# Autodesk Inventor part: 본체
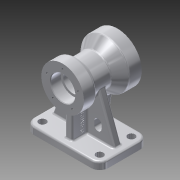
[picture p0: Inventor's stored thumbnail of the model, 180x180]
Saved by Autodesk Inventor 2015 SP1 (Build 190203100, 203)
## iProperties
Created: 2015-08
Part Number: 본체
Material: 알루미늄 6061
Document SubType Name: Modeling
Designer: jun
Density: 2.7 g/cm^3
Appearance: 알루미늄 - 평지
Mass: 1061.97 g
Surface Area: 750.353 cm^2
Volume: 393.324 cm^3
Author: jun
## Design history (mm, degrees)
sketch "스케치1"
  geometry: L1 (-61, 40)-(61, 40); L2 (61, 40)-(61, -40); L3 (61, -40)-(-61, -40); L4 (-61, -40)-(-61, 40); L5 (-61, 40)-(61, -40); 2 further points
  constraints: 10 end point, 2 parallel, 1 coincident, 1 horizontal, 1 midpoint, 1 perpendicular
  dimensions: "d0" = 122 distance of L1.start L1.end; "d1" = 80 distance of L1.end L2.end
extrude "돌출1" new body sketch "스케치1" distance "d2" = 12; taper "d3" = 0 deg
sketch "스케치2"
  geometry: L1 (40, 12)-(40, 0) reference; L2 (40, 0)-(-40, 0) reference; L3 (-40, 0)-(-40, 12) reference; L4 (-40, 12)-(40, 12) reference; L5 (50, 90)-(-40, 90); L6 (50, 90)-(50, 50); L7 (50, 50)-(30, 50); L8 (-40, 90)-(-40, 55); L9 (-40, 55)-(-20, 55); L10 (30, 50)-(13.315, 64); L11 (13.315, 64)-(-14.804, 64); L12 (-14.804, 64)-(-20, 55); L13 (-40, 0)-(-40, 12) reference; 2 further points
  constraints: 16 end point, 2 horizontal, 2 perpendicular, 2 vertical, 1 midpoint, 1 vertical alignment
  dimensions: "d8" = 35 distance of L5.end L8.end; "d9" = 20 distance of L8.end L9.end; "d16" = 60 deg angle of L12 L11; "d103" = 90 distance of L5.start L5.end; "d106" = 90 distance between parallel lines of L2 L5; "d107" = 20 distance of L6.end L7.end; "d108" = 40 deg angle of L10 L11; "d109" = 26 distance between parallel lines of L5 L11; "d110" = 40 distance of L5.start L6.end
revolve "회전1" sketch "스케치2" stored, may be unused: angle "d17" = 90 deg
sketch "스케치3"
  geometry: L1 (61, 12)-(61, 0) reference; L2 (61, 0)-(-61, 0) reference; L3 (-61, 0)-(-61, 12) reference; L4 (-61, 12)-(61, 12) reference; L5 (-25.091, 83.185)-(-51, 12); L6 (-51, 12)-(51, 12); L7 (61, 12)-(-61, 12) reference; L8 (51, 12)-(25.091, 83.185); A1 r 26 centre (0, 90) between (-25.091, 83.185) and (25.091, 83.185) reference; A2 r 26 centre (0, 90) between (-25.091, 83.185) and (25.091, 83.185) reference; 1 further point
  constraints: 6 end point, 4 point on circle, 2 point on line
  dimensions: "d18" = 70 deg angle of L4 L8; "d19" = 70 deg angle of L4 L5; "d20" = 10 distance from line of L3 L5.end; "d21" = 10 distance from line of L1 L6.end
extrude "돌출2" join sketch "스케치3" stored distance "d22" = 12; taper "d23" = 0 deg
sketch "스케치4"
  geometry: L1 (40, 12)-(40, 0) reference; L2 (40, 0)-(-40, 0) reference; L3 (-40, 0)-(-40, 12) reference; L4 (-40, 12)-(-6, 12) reference; L5 (-6, 12)-(-6, 64) reference; L6 (-6, 64)-(-14.804, 64) reference; L7 (-14.804, 64)-(-20, 55) reference; L8 (-20, 55)-(-40, 55) reference; L9 (-40, 55)-(-40, 125) reference; L10 (-40, 125)-(-20, 125) reference; L11 (-20, 125)-(-14.804, 116) reference; L12 (-14.804, 116)-(13.315, 116) reference; L13 (13.315, 116)-(30, 130) reference; L14 (30, 130)-(50, 130) reference; L15 (50, 130)-(50, 50) reference; L16 (50, 50)-(30, 50) reference; L17 (30, 50)-(13.315, 64) reference; L18 (13.315, 64)-(6, 64) reference; L19 (6, 64)-(6, 12) reference; L20 (6, 12)-(40, 12) reference; L21 (-30, 55)-(-30, 12); L22 (36.7, 50)-(30, 12); L23 (40, 12)-(-40, 12) reference; 1 further point
  constraints: 4 end point, 3 point on line, 1 midpoint, 1 perpendicular
  dimensions: "d24" = 80 deg angle of L23 L22; "d25" = 10 distance from line of L22.end L1; "d26" = 10 distance between parallel lines of L3 L21
  node "절단 모서리 투영3"
feature "리브1" dims "d27" = 1, "d28" = 12, "d29" = 0, "d30" = 0, "d31" = 1, "d32" = 1
feature "리브2" dims "d33" = 1, "d34" = 12, "d35" = 0, "d36" = 0, "d37" = 1, "d38" = 1
sketch "스케치5"
  geometry: C1 r 40 at (0, 0) reference; C2 r 26 at (0, 0); 1 further point
  constraints: 1 centre point, 1 coincident
  dimensions: "d39" = 52 diameter of C2
extrude "돌출3" cut sketch "스케치5" distance "d40" = 20; taper "d41" = 0 deg
sketch "스케치6"
  geometry: L1 (-6, 39.547)-(-6, 78) reference; L2 (-6, 78)-(-61, 78) reference; L3 (-61, 78)-(-61, 90) reference; L4 (-61, 90)-(61, 90) reference; L5 (61, 90)-(61, 78) reference; L6 (61, 78)-(6, 78) reference; L7 (6, 78)-(6, 39.547) reference; L8 (6, 78)-(-6, 78) reference; C1 r 26 at (0, 0) reference; C2 r 19 at (0, 0); A1 r 40 centre (0, 0) between (-6, 39.547) and (6, 39.547) reference; 1 further point
  constraints: 1 centre point, 1 coincident
  dimensions: "d42" = 38 diameter of C2
extrude "돌출4" cut sketch "스케치6" distance "d43" = 3; taper "d44" = 0 deg
sketch "스케치7"
  geometry: L1 (-6, 78)-(-61, 78) reference; L2 (-61, 78)-(-61, 90) reference; L3 (-61, 90)-(61, 90) reference; L4 (61, 90)-(61, 78) reference; L5 (61, 78)-(6, 78) reference; L6 (6, 78)-(6, 36.999) reference; L7 (-6, 36.999)-(-6, 78) reference; C1 r 19 at (0, 0) reference; C2 r 16 at (0, 0); A1 r 37.483 centre (0, 0) between (-6, 36.999) and (6, 36.999) reference; 1 further point
  constraints: 1 centre point, 1 coincident
  dimensions: "d45" = 32 diameter of C2
extrude "돌출5" cut sketch "스케치7" stored distance "d46" = 3; taper "d47" = 0 deg
sketch "스케치8"
  geometry: L1 (-61, -78)-(61, -78) reference; L2 (61, -78)-(61, -90) reference; L3 (61, -90)-(-61, -90) reference; L4 (-61, -90)-(-61, -78) reference; C1 r 16 at (0, 0) reference; C2 r 35 at (0, 0) reference; C3 r 20 at (0, 0); 1 further point
  constraints: 1 centre point, 1 coincident
  dimensions: "d48" = 40 diameter of C3
extrude "돌출6" cut sketch "스케치8" distance "d49" = 17; taper "d50" = 0 deg
sketch "스케치9"
  geometry: C1 r 26 at (0, 0) reference; C2 r 40 at (0, 0) reference; 2 further points
  constraints: 1 vertical alignment
  dimensions: "d51" = 33 distance of C1.centre point (0, -33)
hole "구멍1" sketch "스케치9" at (0, -33) diameter "d52" = 3.242; stored, may be unused: countersink angle "d56" = 90 deg, drill point angle "d58" = 118 deg; dims "d53" = 10, "d54" = 4, "d55" = 2, "d57" = 13
sketch "스케치10"
  geometry: L1 (-61, -78)-(61, -78) reference; L2 (61, -78)-(61, -90) reference; L3 (61, -90)-(-61, -90) reference; L4 (-61, -90)-(-61, -78) reference; C1 r 20 at (0, 0) reference; C2 r 35 at (0, 0) reference; 2 further points
  constraints: 1 vertical alignment
  dimensions: "d62" = 27 distance of C1.centre point (0, 27)
hole "구멍2" sketch "스케치10" at (0, 27) diameter "d63" = 3.242; stored, may be unused: countersink angle "d67" = 90 deg, drill point angle "d69" = 118 deg; dims "d64" = 10, "d65" = 4, "d66" = 2, "d68" = 13
sketch "스케치11"
  geometry: L1 (-6, -64.702)-(-6, -12) reference; L2 (-6, -12)-(-51, -12) reference; L3 (-25.091, -83.185)-(-51, -12) reference; L4 (6, -12)-(6, -64.702) reference; L5 (51, -12)-(6, -12) reference; L6 (61, -12)-(51, -12) reference; L7 (61, 0)-(61, -12) reference; L8 (-61, 0)-(61, 0) reference; L9 (-61, -12)-(-61, 0) reference; L10 (-51, -12)-(-61, -12) reference; L11 (51, -12)-(25.091, -83.185) reference; L12 (24, -42)-(24, -24); L13 (30, -36)-(30, -30); L14 (18, -30)-(18, -36); L15 (0, 0)-(0, -64.702); C1 r 16 at (0, -90) reference; A1 r 26 centre (0, -90) between (25.091, -83.185) and (6, -64.702) reference; A2 r 26 centre (0, -90) between (-25.091, -83.185) and (25.091, -83.185) reference; A3 r 26 centre (0, -90) between (-6, -64.702) and (-25.091, -83.185) reference; A4 r 6 centre (24, -36) between (18, -36) and (30, -36); A5 r 6 centre (24, -30) between (30, -30) and (18, -30)
  constraints: 10 end point, 6 point on circle, 4 tangent, 2 centre point, 2 point on line, 2 vertical, 1 parallel
  dimensions: "d73" = 18 distance from line of A5.centre L5; "d74" = 18 distance of L12.end L12.start; "d75" = 12 distance of L14.end L13.start; "d76" = 24 distance from line of L15 A5.centre
extrude "돌출7" cut sketch "스케치11" stored distance "d77" = 17; taper "d78" = 0 deg
fillet "모깎기1" dims "d79" = 14
fillet "모깎기2" dims "d80" = 3
sketch "스케치12"
  geometry: L1 (-47, -37)-(47, -37) reference; L2 (58, -26)-(58, 26) reference; L3 (47, 37)-(-47, 37) reference; L4 (-58, 26)-(-58, -26) reference; L5 (-6, 30)-(6, 30) reference; L6 (6, 30)-(6, 6) reference; L7 (6, 6)-(51, 6) reference; L8 (51, 6)-(51, -6) reference; L9 (51, -6)-(6, -6) reference; L10 (6, -6)-(6, -30) reference; L11 (6, -30)-(-6, -30) reference; L12 (-6, -30)-(-6, -6) reference; L13 (-6, -6)-(-51, -6) reference; L14 (-51, -6)-(-51, 6) reference; L15 (-51, 6)-(-6, 6) reference; L16 (-6, 6)-(-6, 30) reference; C1 r 6 at (47, 26); C2 r 6 at (47, -26); C3 r 6 at (-47, -26); C4 r 6 at (-47, 26); A1 r 11 centre (47, -26) between (47, -37) and (58, -26) reference; A2 r 11 centre (47, 26) between (58, 26) and (47, 37) reference; A3 r 11 centre (-47, 26) between (-47, 37) and (-58, 26) reference; A4 r 11 centre (-47, -26) between (-58, -26) and (-47, -37) reference; 1 further point
  constraints: 4 centre point, 4 coincident
  dimensions: "d81" = 12 diameter of C1; "d82" = 12 diameter of C2; "d83" = 12 diameter of C3; "d84" = 12 diameter of C4
extrude "돌출8" cut sketch "스케치12" stored distance "d85" = 17; taper "d86" = 0 deg
fillet "모깎기3" dims "d87" = 3
fillet "모깎기4" dims "d88" = 3
fillet "모깎기5" dims "d89" = 3
fillet "모깎기6" dims "d90" = 3
fillet "모깎기7" dims "d91" = 5
fillet "모깎기8" dims "d92" = 5
fillet "모깎기9" dims "d93" = 0.3
fillet "모깎기10" dims "d94" = 3
chamfer "모따기1" distance "d95" = 1; stored, may be unused: second distance "d96" = 2, angle "d97" = 45 deg
sketch "스케치13"
  geometry: L1 (3, -10)-(3, 1) reference; L2 (-37.119, -3)-(0, -3) reference; 2 further points
  constraints: 1 other
  dimensions: "d98" = 24 distance from line of point (-21, 13) L1; "d99" = 16 distance from line of L2 point (-21, 13)
feature "엠보싱1" sketch "스케치13" dims "d0" = 122, "d1" = 80, "d100" = 0.5, "d101" = 0
node "솔리드1"
pattern_circular "원형 패턴1" dims angle "d60" = 360 deg
pattern_circular "원형 패턴2" dims angle "d71" = 360 deg
mirror "대칭1"
node "절단 모서리 투영1"
node "절단 모서리 투영2"
node "절단 모서리 투영4"
node "절단 모서리 투영5"
node "절단 모서리 투영6"
node "절단 모서리 투영7"
node "절단 모서리 투영8"
node "절단 모서리 투영9"
node "절단 모서리 투영10"
node "절단 모서리 투영11"
